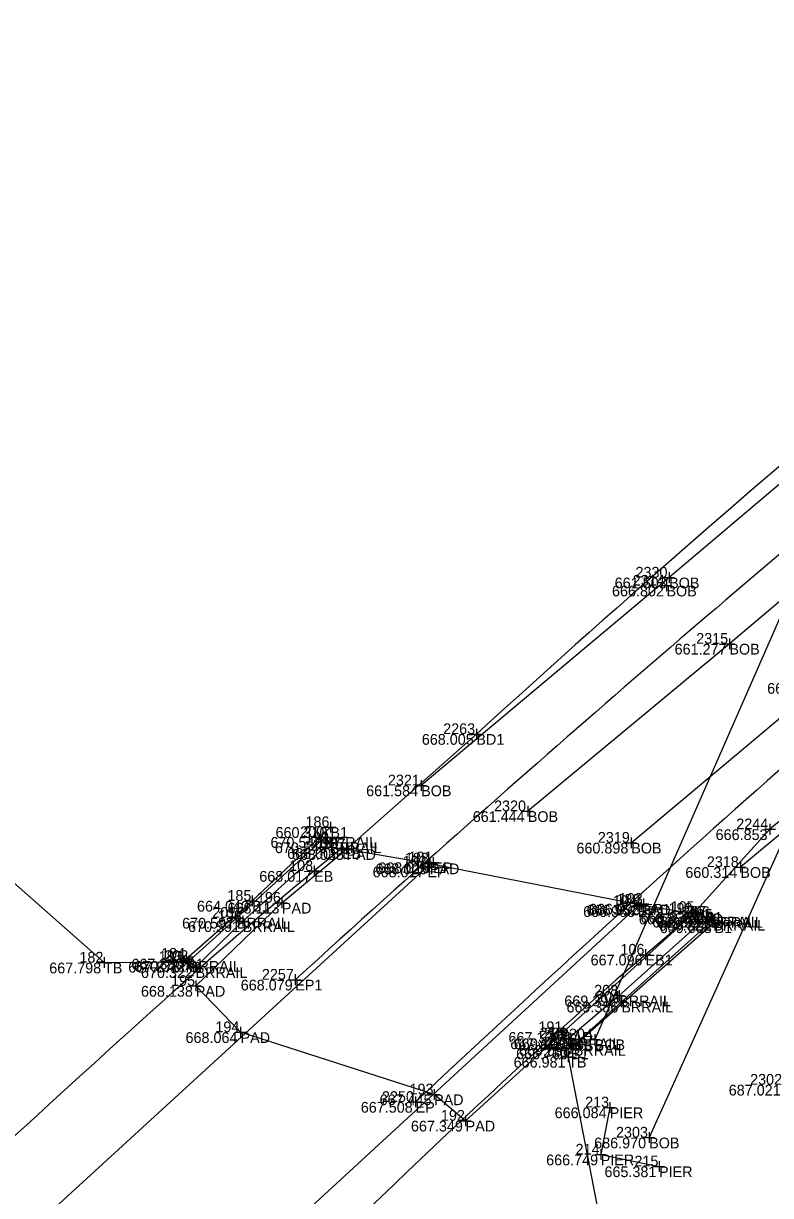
# Model space of a CAD drawing. Extents: x 2197382 to 2204062, y 634117 to 636522.
# Drawn here: x 2202513 to 2202582.6, y 635122.7 to 635231.8 of the extents above; entities that cross this region are included whole.
import ezdxf

# ---------------------------------------------------------------- set-up
doc = ezdxf.new("R2010")
doc.units = 0
for name, color, linetype in [('_CIVIL_CONSTRUCTION', 7, 'Continuous'), ('BR_P_Gen_Approach_Slab', 7, 'Continuous'), ('BR_X_SV_Bottom_of_Beam', 7, 'Continuous'), ('BR_X_SV_Bottom_of_Beam_Text', 7, 'Continuous'), ('BR_X_SV_Deck_Top', 7, 'Continuous'), ('BR_X_SV_Deck_Top_Text', 7, 'Continuous'), ('BR_X_SV_Pier', 7, 'Continuous'), ('BR_X_SV_Rail', 7, 'Continuous'), ('GE_P_Alignment_100_Distances', 7, 'Continuous'), ('GE_X_Alignment', 7, 'Continuous'), ('PF_P_Grade_Line', 7, 'Continuous'), ('RW_X_CL_100_Distances', 7, 'Continuous'), ('RW_X_CL_100_Stations', 7, 'Continuous'), ('SH_Border', 7, 'Continuous'), ('SH_Cut_Line', 7, 'Continuous'), ('SH_Data', 7, 'Continuous'), ('SH_Text', 7, 'Continuous')]:
    doc.layers.add(name, color=color, linetype=linetype)

msp = doc.modelspace()

# ---------------------------------------------------------------- linework, layer by layer
at = {"layer": '_CIVIL_CONSTRUCTION'}
for p, q in [((2202572.62, 635180.24), (2202573.62, 635180.24)), ((2202572.87, 635179.99), (2202572.87, 635178.99)), ((2202573.12, 635180.74), (2202573.12, 635179.74)), ((2202573.12, 635180.24), (2202573.12, 635180.24)), ((2202572.37, 635179.49), (2202573.37, 635179.49)), ((2202572.87, 635179.49), (2202572.87, 635179.49)), ((2202578.73, 635174.58), (2202578.73, 635173.58)), ((2202578.23, 635174.08), (2202579.23, 635174.08)), ((2202578.73, 635174.08), (2202578.73, 635174.08)), ((2202554.67, 635165.67), (2202555.67, 635165.67)), ((2202555.17, 635166.17), (2202555.17, 635165.17)), ((2202555.17, 635165.67), (2202555.17, 635165.67)), ((2202550.03, 635161.39), (2202550.03, 635160.39)), ((2202549.53, 635160.89), (2202550.53, 635160.89)), ((2202550.03, 635160.89), (2202550.03, 635160.89)), ((2202559.96, 635158.99), (2202559.96, 635157.99)), ((2202559.46, 635158.49), (2202560.46, 635158.49)), ((2202559.96, 635158.49), (2202559.96, 635158.49)), ((2202541.08, 635157.01), (2202542.08, 635157.01)), ((2202541.58, 635157.51), (2202541.58, 635156.51)), ((2202541.58, 635157.01), (2202541.58, 635157.01)), ((2202582.01, 635156.81), (2202583.01, 635156.81)), ((2202582.51, 635157.31), (2202582.51, 635156.31)), ((2202582.51, 635156.81), (2202582.51, 635156.81)), ((2202540.6, 635156.09), (2202541.6, 635156.09)), ((2202541.1, 635156.59), (2202541.1, 635155.59)), ((2202541.1, 635156.09), (2202541.1, 635156.09)), ((2202541.52, 635156.09), (2202541.52, 635155.09)), ((2202569.59, 635156.06), (2202569.59, 635155.06)), ((2202541.02, 635155.59), (2202542.02, 635155.59)), ((2202541.52, 635155.59), (2202541.52, 635155.59)), ((2202542.16, 635155.06), (2202543.16, 635155.06)), ((2202542.57, 635154.96), (2202543.57, 635154.96)), ((2202542.66, 635155.56), (2202542.66, 635154.56)), ((2202542.66, 635155.06), (2202542.66, 635155.06)), ((2202543.07, 635155.46), (2202543.07, 635154.46)), ((2202543.07, 635154.96), (2202543.07, 635154.96)), ((2202569.09, 635155.56), (2202570.09, 635155.56)), ((2202569.59, 635155.56), (2202569.59, 635155.56)), ((2202550.34, 635153.63), (2202551.34, 635153.63)), ((2202550.61, 635153.84), (2202550.61, 635152.84)), ((2202550.64, 635153.73), (2202551.64, 635153.73)), ((2202550.84, 635154.13), (2202550.84, 635153.13)), ((2202550.84, 635153.63), (2202550.84, 635153.63)), ((2202551.14, 635154.23), (2202551.14, 635153.23)), ((2202551.14, 635153.73), (2202551.14, 635153.73)), ((2202579.75, 635153.79), (2202579.75, 635152.79)), ((2202539.56, 635152.93), (2202540.56, 635152.93)), ((2202540.06, 635153.43), (2202540.06, 635152.43)), ((2202540.06, 635152.93), (2202540.06, 635152.93)), ((2202550.11, 635153.34), (2202551.11, 635153.34)), ((2202550.61, 635153.34), (2202550.61, 635153.34)), ((2202579.25, 635153.29), (2202580.25, 635153.29)), ((2202579.75, 635153.29), (2202579.75, 635153.29)), ((2202534.28, 635150.65), (2202534.28, 635149.65)), ((2202537.06, 635150.47), (2202537.06, 635149.47)), ((2202570.51, 635150.29), (2202570.51, 635149.29)), ((2202570.72, 635150.37), (2202570.72, 635149.37)), ((2202533.78, 635150.15), (2202534.78, 635150.15)), ((2202534.28, 635150.15), (2202534.28, 635150.15)), ((2202536.56, 635149.97), (2202537.56, 635149.97)), ((2202537.06, 635149.97), (2202537.06, 635149.97)), ((2202569.71, 635149.65), (2202570.71, 635149.65)), ((2202570.01, 635149.79), (2202571.01, 635149.79)), ((2202570.21, 635150.15), (2202570.21, 635149.15)), ((2202570.21, 635149.65), (2202570.21, 635149.65)), ((2202570.22, 635149.87), (2202571.22, 635149.87)), ((2202570.51, 635149.79), (2202570.51, 635149.79)), ((2202570.72, 635149.87), (2202570.72, 635149.87)), ((2202575.4, 635149.46), (2202575.4, 635148.46)), ((2202575.55, 635149.61), (2202575.55, 635148.61)), ((2202576.65, 635149.17), (2202576.65, 635148.17)), ((2202532.37, 635148.57), (2202533.37, 635148.57)), ((2202532.87, 635149.07), (2202532.87, 635148.07)), ((2202532.87, 635148.57), (2202532.87, 635148.57)), ((2202532.92, 635148.25), (2202533.92, 635148.25)), ((2202533.42, 635148.75), (2202533.42, 635147.75)), ((2202533.42, 635148.25), (2202533.42, 635148.25)), ((2202574.9, 635148.96), (2202575.9, 635148.96)), ((2202575.05, 635149.11), (2202576.05, 635149.11)), ((2202575.4, 635148.96), (2202575.4, 635148.96)), ((2202575.55, 635149.11), (2202575.55, 635149.11)), ((2202576.15, 635148.67), (2202577.15, 635148.67)), ((2202576.51, 635148.64), (2202577.51, 635148.64)), ((2202576.65, 635148.67), (2202576.65, 635148.67)), ((2202576.73, 635148.38), (2202577.73, 635148.38)), ((2202576.85, 635148.15), (2202577.85, 635148.15)), ((2202577.01, 635149.14), (2202577.01, 635148.14)), ((2202577.01, 635148.64), (2202577.01, 635148.64)), ((2202577.23, 635148.88), (2202577.23, 635147.88)), ((2202577.23, 635148.38), (2202577.23, 635148.38)), ((2202577.35, 635148.65), (2202577.35, 635147.65)), ((2202577.35, 635148.15), (2202577.35, 635148.15)), ((2202520.5, 635144.9), (2202520.5, 635143.9)), ((2202527.86, 635144.97), (2202527.86, 635143.97)), ((2202528.16, 635145.26), (2202528.16, 635144.26)), ((2202528.4, 635145.05), (2202528.4, 635144.05)), ((2202570.42, 635145.14), (2202571.42, 635145.14)), ((2202570.92, 635145.64), (2202570.92, 635144.64)), ((2202570.92, 635145.14), (2202570.92, 635145.14)), ((2202520, 635144.4), (2202521, 635144.4)), ((2202520.5, 635144.4), (2202520.5, 635144.4)), ((2202527.36, 635144.47), (2202528.36, 635144.47)), ((2202527.66, 635144.76), (2202528.66, 635144.76)), ((2202527.86, 635144.47), (2202527.86, 635144.47)), ((2202527.9, 635144.55), (2202528.9, 635144.55)), ((2202528.16, 635144.76), (2202528.16, 635144.76)), ((2202528.4, 635144.55), (2202528.4, 635144.55)), ((2202528.52, 635143.97), (2202529.52, 635143.97)), ((2202529.02, 635144.47), (2202529.02, 635143.47)), ((2202529.02, 635143.97), (2202529.02, 635143.97)), ((2202529.04, 635142.73), (2202529.04, 635141.73)), ((2202537.81, 635142.81), (2202538.81, 635142.81)), ((2202538.31, 635143.31), (2202538.31, 635142.31)), ((2202538.31, 635142.81), (2202538.31, 635142.81)), ((2202528.54, 635142.23), (2202529.54, 635142.23)), ((2202529.04, 635142.23), (2202529.04, 635142.23)), ((2202568.46, 635141.83), (2202568.46, 635140.83)), ((2202567.96, 635141.33), (2202568.96, 635141.33)), ((2202568.17, 635140.76), (2202569.17, 635140.76)), ((2202568.46, 635141.33), (2202568.46, 635141.33)), ((2202568.67, 635141.26), (2202568.67, 635140.26)), ((2202568.67, 635140.76), (2202568.67, 635140.76)), ((2202533.21, 635138.42), (2202533.21, 635137.42)), ((2202563.26, 635138.43), (2202563.26, 635137.43)), ((2202532.71, 635137.92), (2202533.71, 635137.92)), ((2202533.21, 635137.92), (2202533.21, 635137.92)), ((2202562.76, 635137.93), (2202563.76, 635137.93)), ((2202562.9, 635137.35), (2202563.9, 635137.35)), ((2202563.25, 635137.34), (2202564.25, 635137.34)), ((2202563.26, 635137.93), (2202563.26, 635137.93)), ((2202563.4, 635137.85), (2202563.4, 635136.85)), ((2202563.4, 635137.35), (2202563.4, 635137.35)), ((2202563.75, 635137.84), (2202563.75, 635136.84)), ((2202563.75, 635137.34), (2202563.75, 635137.34)), ((2202564.24, 635137.23), (2202564.24, 635136.23)), ((2202565.69, 635137.25), (2202566.69, 635137.25)), ((2202566.19, 635137.75), (2202566.19, 635136.75)), ((2202566.19, 635137.25), (2202566.19, 635137.25)), ((2202563.48, 635136.4), (2202564.48, 635136.4)), ((2202563.72, 635136.13), (2202563.72, 635135.13)), ((2202563.74, 635136.73), (2202564.74, 635136.73)), ((2202563.98, 635136.9), (2202563.98, 635135.9)), ((2202563.98, 635136.4), (2202563.98, 635136.4)), ((2202564.24, 635136.73), (2202564.24, 635136.73)), ((2202563.22, 635135.63), (2202564.22, 635135.63)), ((2202563.72, 635135.63), (2202563.72, 635135.63)), ((2202549.51, 635131.93), (2202549.51, 635130.93)), ((2202550.73, 635132.13), (2202551.73, 635132.13)), ((2202551.23, 635132.63), (2202551.23, 635131.63)), ((2202551.23, 635132.13), (2202551.23, 635132.13)), ((2202549.01, 635131.43), (2202550.01, 635131.43)), ((2202549.51, 635131.43), (2202549.51, 635131.43)), ((2202567.09, 635130.92), (2202568.09, 635130.92)), ((2202567.59, 635131.42), (2202567.59, 635130.42)), ((2202567.59, 635130.92), (2202567.59, 635130.92)), ((2202553.67, 635129.68), (2202554.67, 635129.68)), ((2202554.17, 635130.18), (2202554.17, 635129.18)), ((2202554.17, 635129.68), (2202554.17, 635129.68)), ((2202571.26, 635128.61), (2202571.26, 635127.61)), ((2202570.76, 635128.11), (2202571.76, 635128.11)), ((2202571.26, 635128.11), (2202571.26, 635128.11)), ((2202566.25, 635126.53), (2202567.25, 635126.53)), ((2202566.75, 635127.03), (2202566.75, 635126.03)), ((2202566.75, 635126.53), (2202566.75, 635126.53)), ((2202571.68, 635125.43), (2202572.68, 635125.43)), ((2202572.18, 635125.93), (2202572.18, 635124.93)), ((2202572.18, 635125.43), (2202572.18, 635125.43))]:
    msp.add_line(p, q, dxfattribs=at)
at = {"layer": 'BR_P_Gen_Approach_Slab'}
msp.add_lwpolyline([(2202543.07, 635154.96), (2202550.84, 635153.63), (2202570.51, 635149.79), (2202575.4, 635148.96), (2202563.26, 635137.93), (2202554.17, 635129.68), (2202551.23, 635132.13), (2202533.21, 635137.92), (2202529.04, 635142.23), (2202537.06, 635149.97)], close=True, dxfattribs=at)
at = {"layer": 'BR_X_SV_Bottom_of_Beam'}
for points in [[(2202698.74, 635432.34), (2202647, 635318.77), (2202622.9, 635265.64), (2202604.22, 635223.89), (2202566.19, 635137.25)], [(2202700.3, 635413.56), (2202652.91, 635308.89), (2202632.96, 635265.28), (2202616.35, 635228.13), (2202571.26, 635128.11)], [(2202606.61, 635208.62), (2202603.7, 635205.92), (2202603.43, 635205.67), (2202587.81, 635192.67), (2202573.12, 635180.24), (2202550.03, 635160.89)], [(2202617.23, 635206.4), (2202614, 635203.65), (2202596.42, 635189.02), (2202578.73, 635174.08), (2202559.96, 635158.49)], [(2202569.59, 635155.56), (2202587.35, 635170.43), (2202603.51, 635184.09), (2202612.29, 635191.47), (2202624.52, 635201.84), (2202627.43, 635204.04)], [(2202639.19, 635203), (2202635.46, 635199.72), (2202613.03, 635181.1), (2202603.37, 635172.99), (2202595.3, 635166.21), (2202579.75, 635153.29)]]:
    msp.add_lwpolyline(points, dxfattribs=at)
at = {"layer": 'BR_X_SV_Deck_Top'}
for p, q in [((2202555.17, 635165.67), (2202543.07, 635154.96)), ((2202582.51, 635156.81), (2202575.4, 635148.96))]:
    msp.add_line(p, q, dxfattribs=at)
for points in [[(2202458.05, 635216.68), (2202477.12, 635219.98), (2202511.72, 635243.78), (2202554.96, 635262.3), (2202588.01, 635280.67), (2202608.34, 635292.39), (2202640.83, 635312.14), (2202668.15, 635329.95), (2202698.57, 635351.31), (2202722.13, 635368.65), (2202754.6, 635393.43), (2202777.49, 635412.29), (2202789.61, 635422.64)], [(2202895.36, 635391.81), (2202885.35, 635387.33), (2202865.19, 635377.21), (2202839.04, 635363.76), (2202813.1, 635349.72), (2202789.18, 635336.14), (2202762.39, 635320.29), (2202740.67, 635306.56), (2202716.63, 635290.83), (2202693.39, 635275.34), (2202664.57, 635254.79), (2202633.54, 635231.77), (2202595.89, 635201.64), (2202569.4, 635178.62), (2202555.17, 635165.67)], [(2202923.18, 635376.2), (2202906.17, 635369.08), (2202881.49, 635355.93), (2202846.74, 635338.13), (2202819.01, 635322.65), (2202790.14, 635306.09), (2202754.02, 635283.78), (2202709.42, 635255.58), (2202663.28, 635220.88), (2202620.57, 635187.91), (2202595.28, 635167.4), (2202582.51, 635156.81)]]:
    msp.add_open_spline(points, degree=3, dxfattribs=at)
at = {"layer": 'BR_X_SV_Pier'}
msp.add_lwpolyline([(2202567.59, 635130.92), (2202566.75, 635126.53), (2202572.18, 635125.43)], dxfattribs=at)
at = {"layer": 'BR_X_SV_Rail'}
for points in [[(2202529.02, 635143.97), (2202533.42, 635148.25), (2202541.52, 635155.59), (2202541.1, 635156.09), (2202532.87, 635148.57), (2202528.4, 635144.55)], [(2202564.24, 635136.73), (2202568.67, 635140.76), (2202577.23, 635148.38), (2202577.01, 635148.64), (2202576.65, 635148.67), (2202568.46, 635141.33), (2202563.75, 635137.34)]]:
    msp.add_lwpolyline(points, close=True, dxfattribs=at)
at = {"layer": 'GE_P_Alignment_100_Distances'}
for p, q in [((2202551.14, 635153.73), (2202550.61, 635153.34)), ((2202550.61, 635153.34), (2202514.19, 635120)), ((2202570.21, 635149.65), (2202525.02, 635108.11)), ((2202570.72, 635149.87), (2202570.21, 635149.65))]:
    msp.add_line(p, q, dxfattribs=at)
for points in [[(2202457.67, 635223.28), (2202466.48, 635226.87), (2202500.46, 635242.35), (2202539.48, 635261.18), (2202573.06, 635279.52), (2202585.61, 635286.63), (2202599.84, 635294.84), (2202617.62, 635305.23), (2202642.29, 635320.4), (2202667.37, 635336.77), (2202691.72, 635353.63), (2202713.41, 635369.4), (2202739.64, 635388.97), (2202758.66, 635404.28), (2202770.06, 635413.81)], [(2202926.99, 635398.22), (2202911.05, 635391.27), (2202884.78, 635379.22), (2202850.25, 635362.17), (2202828.22, 635350.04), (2202808.09, 635339.2), (2202790.85, 635329.04), (2202764, 635313.32), (2202738.78, 635297.64), (2202713.05, 635280.58), (2202697.02, 635269.6), (2202684.53, 635260.86), (2202668.99, 635249.75), (2202642.65, 635230.81), (2202596.56, 635193.89), (2202560.68, 635163.16), (2202538.31, 635142.81)], [(2202919.5, 635378.37), (2202901.45, 635370.68), (2202875.94, 635356.88), (2202844.59, 635341.6), (2202825.86, 635330.82), (2202809.47, 635322.02), (2202780.05, 635304.41), (2202746.06, 635283), (2202707.72, 635258.18), (2202682.24, 635240.21), (2202658.95, 635222.26), (2202614.14, 635189.25), (2202577.35, 635157.52), (2202549.51, 635131.43)]]:
    msp.add_open_spline(points, degree=3, dxfattribs=at)
at = {"layer": 'GE_X_Alignment'}
for p, q in [((2202542.66, 635155.06), (2202540.06, 635152.93)), ((2202575.55, 635149.11), (2202570.92, 635145.14))]:
    msp.add_line(p, q, dxfattribs=at)
for points in [[(2202540.06, 635152.93), (2202529.43, 635144.25), (2202507.23, 635123.46), (2202471.72, 635092.05), (2202435.62, 635056.76), (2202402.1, 635018.87), (2202368.73, 634981.48), (2202336.15, 634943.25), (2202304.62, 634904.21), (2202274.11, 634864.33), (2202244.37, 634823.83), (2202215.65, 634782.83), (2202187.65, 634741.05), (2202161.54, 634698.56), (2202134.84, 634656), (2202111.41, 634611.66), (2202087.71, 634567.52), (2202064.97, 634523.35), (2202044.2, 634477.97), (2202023.42, 634432.25), (2202003.66, 634386.18), (2201990.91, 634355.55), (2201984.79, 634340.33)], [(2202570.92, 635145.14), (2202556.1, 635132.41), (2202530.6, 635107.02), (2202492.19, 635071.28), (2202457.98, 635035.82), (2202424.73, 634999.38), (2202391.64, 634962.22), (2202359.56, 634924.46), (2202328.32, 634885.6), (2202298.37, 634846.53), (2202268.85, 634806.21), (2202240.94, 634765.59), (2202212.91, 634724.71), (2202187.2, 634682.69), (2202161.14, 634640.35), (2202137.99, 634596.95), (2202114.64, 634553.56), (2202092.28, 634509.95), (2202071.73, 634464.7), (2202050.81, 634420.11), (2202031.84, 634374.34), (2202014.23, 634328.21), (2201997.98, 634281.03), (2201983.22, 634233.69), (2201972.74, 634202.38), (2201968.03, 634186.79)]]:
    msp.add_open_spline(points, degree=3, dxfattribs=at)
at = {"layer": 'PF_P_Grade_Line'}
for points in [[(2202484.34, 635172.09), (2202502.01, 635160.7), (2202520.5, 635144.4), (2202527.86, 635144.47)], [(2202563.72, 635135.63), (2202567.86, 635114.33), (2202576.61, 635092), (2202580.49, 635062.03)]]:
    msp.add_lwpolyline(points, dxfattribs=at)
at = {"layer": 'SH_Text'}
for points in [[(2202528.16, 635144.76), (2202534.28, 635150.15), (2202541.58, 635157.01)], [(2202563.4, 635137.35), (2202563.98, 635136.4), (2202577.35, 635148.15)]]:
    msp.add_lwpolyline(points, dxfattribs=at)

# ---------------------------------------------------------------- texts
at = {"layer": 'BR_X_SV_Bottom_of_Beam_Text'}
for s, p in [('2330', (2202569.99, 635180.24)), ('661.503', (2202568.05, 635179.24)), ('2314', (2202569.73, 635179.49)), ('BOB', (2202573.12, 635179.24)), ('666.802', (2202567.8, 635178.49)), ('BOB', (2202572.87, 635178.49)), ('2315', (2202575.64, 635174.08)), ('661.277', (2202573.63, 635173.08)), ('BOB', (2202578.73, 635173.08)), ('660.708', (2202582.25, 635169.43)), ('2321', (2202546.93, 635160.89)), ('661.584', (2202544.91, 635159.89)), ('BOB', (2202550.03, 635159.89)), ('2320', (2202556.82, 635158.49)), ('661.444', (2202554.83, 635157.49)), ('BOB', (2202559.96, 635157.49)), ('2319', (2202566.48, 635155.56)), ('660.898', (2202564.49, 635154.56)), ('BOB', (2202569.59, 635154.56)), ('2318', (2202576.63, 635153.29)), ('660.314', (2202574.63, 635152.29)), ('BOB', (2202579.75, 635152.29)), ('2304', (2202563.05, 635137.25)), ('686.795', (2202561.12, 635136.25)), ('BOB', (2202566.19, 635136.25)), ('2302', (2202580.66, 635133.03)), ('687.021', (2202578.67, 635132.03)), ('2303', (2202568.17, 635128.11)), ('686.970', (2202566.14, 635127.11)), ('BOB', (2202571.26, 635127.11))]:
    msp.add_text(s, height=1, dxfattribs=at).set_placement(p)
at = {"layer": 'BR_X_SV_Deck_Top_Text'}
for s, p in [('2263', (2202552.08, 635165.67)), ('668.005', (2202550.09, 635164.68)), ('BD1', (2202555.17, 635164.68)), ('666.853', (2202577.45, 635155.81)), ('2244', (2202579.37, 635156.81))]:
    msp.add_text(s, height=1, dxfattribs=at).set_placement(p)
at = {"layer": 'RW_X_CL_100_Distances'}
for s, p in [('213', (2202565.3, 635130.92)), ('666.084', (2202562.46, 635129.92)), ('PIER', (2202567.59, 635129.92)), ('214', (2202564.41, 635126.53)), ('666.749', (2202561.67, 635125.53)), ('PIER', (2202566.75, 635125.53)), ('215', (2202569.89, 635125.43)), ('665.381', (2202567.1, 635124.43)), ('PIER', (2202572.18, 635124.43))]:
    msp.add_text(s, height=1, dxfattribs=at).set_placement(p)
at = {"layer": 'RW_X_CL_100_Stations'}
for s, p in [('200', (2202538.77, 635156.09)), ('670.548', (2202536, 635155.09)), ('199', (2202539.21, 635155.59)), ('BRRAIL', (2202541.1, 635155.09)), ('670.546', (2202536.41, 635154.59)), ('BRRAIL', (2202541.52, 635154.59)), ('201', (2202530.57, 635148.57)), ('198', (2202531.09, 635148.25)), ('207', (2202574.34, 635148.67)), ('206', (2202574.68, 635148.64)), ('205', (2202574.94, 635148.38)), ('670.597', (2202527.77, 635147.57)), ('670.591', (2202528.33, 635147.25)), ('BRRAIL', (2202532.87, 635147.57)), ('BRRAIL', (2202533.42, 635147.25)), ('669.328', (2202571.55, 635147.67)), ('669.322', (2202571.93, 635147.64)), ('669.321', (2202572.15, 635147.38)), ('BRRAIL', (2202576.65, 635147.67)), ('BRRAIL', (2202577.01, 635147.64)), ('BRRAIL', (2202577.23, 635147.38)), ('202', (2202526.11, 635144.55)), ('197', (2202526.7, 635143.97)), ('670.321', (2202523.32, 635143.55)), ('670.322', (2202523.94, 635142.97)), ('BRRAIL', (2202528.4, 635143.55)), ('BRRAIL', (2202529.02, 635142.97)), ('208', (2202566.14, 635141.33)), ('204', (2202566.32, 635140.76)), ('669.396', (2202563.36, 635140.33)), ('669.386', (2202563.56, 635139.76)), ('BRRAIL', (2202568.46, 635140.33)), ('BRRAIL', (2202568.67, 635139.76)), ('209', (2202561.44, 635137.34)), ('669.109', (2202558.66, 635136.34)), ('203', (2202561.95, 635136.73)), ('BRRAIL', (2202563.75, 635136.34)), ('669.098', (2202559.14, 635135.73)), ('BRRAIL', (2202564.24, 635135.73))]:
    msp.add_text(s, height=1, dxfattribs=at).set_placement(p)
at = {"layer": 'SH_Border'}
for s, p in [('B1', (2202541.58, 635156.01)), ('EB', (2202542.66, 635154.06)), ('PAD', (2202543.07, 635153.96)), ('PAD', (2202550.84, 635152.63)), ('EP', (2202551.14, 635152.73)), ('EB', (2202540.06, 635151.93)), ('EP', (2202550.61, 635152.34)), ('B1', (2202534.28, 635149.15)), ('PAD', (2202537.06, 635148.97)), ('EP1', (2202570.21, 635148.65)), ('PAD', (2202570.51, 635148.79)), ('EP1', (2202570.72, 635148.87)), ('PAD', (2202575.4, 635147.96)), ('EB1', (2202575.55, 635148.11)), ('B1', (2202577.35, 635147.15)), ('EB1', (2202570.92, 635144.14)), ('TB', (2202520.5, 635143.4)), ('TB', (2202527.86, 635143.47)), ('B1', (2202528.16, 635143.76)), ('EP1', (2202538.31, 635141.81)), ('PAD', (2202529.04, 635141.23)), ('PAD', (2202533.21, 635136.92)), ('PAD', (2202563.26, 635136.93)), ('B1', (2202563.4, 635136.35)), ('B1', (2202563.98, 635135.4)), ('TB', (2202563.72, 635134.63)), ('PAD', (2202551.23, 635131.13)), ('EP', (2202549.51, 635130.43)), ('PAD', (2202554.17, 635128.68))]:
    msp.add_text(s, height=1, dxfattribs=at).set_placement(p)
at = {"layer": 'SH_Cut_Line'}
for s, p in [('186', (2202539.26, 635157.01)), ('107', (2202540.34, 635155.06)), ('187', (2202540.76, 635154.96)), ('188', (2202548.52, 635153.63)), ('101', (2202548.84, 635153.73)), ('108', (2202537.74, 635152.93)), ('102', (2202548.31, 635153.34)), ('185', (2202531.99, 635150.15)), ('196', (2202534.74, 635149.97)), ('104', (2202567.87, 635149.65)), ('189', (2202568.21, 635149.79)), ('103', (2202568.43, 635149.87)), ('190', (2202573.06, 635148.96)), ('105', (2202573.26, 635149.11)), ('212', (2202575.06, 635148.15)), ('106', (2202568.59, 635145.14)), ('182', (2202518.21, 635144.4)), ('183', (2202525.58, 635144.47)), ('184', (2202525.82, 635144.76)), ('2257', (2202535.2, 635142.81)), ('195', (2202526.75, 635142.23)), ('194', (2202530.87, 635137.92)), ('191', (2202560.95, 635137.93)), ('210', (2202561.06, 635137.35)), ('211', (2202561.68, 635136.4)), ('216', (2202561.4, 635135.63)), ('193', (2202548.95, 635132.13)), ('2250', (2202546.38, 635131.43)), ('192', (2202551.87, 635129.68))]:
    msp.add_text(s, height=1, dxfattribs=at).set_placement(p)
at = {"layer": 'SH_Data'}
for s, p in [('660.310', (2202536.47, 635156.01)), ('668.006', (2202537.55, 635154.06)), ('668.035', (2202538, 635153.96)), ('668.025', (2202545.77, 635152.63)), ('668.010', (2202546.03, 635152.73)), ('668.017', (2202534.96, 635151.93)), ('668.017', (2202545.51, 635152.34)), ('664.040', (2202529.16, 635149.15)), ('668.113', (2202532, 635148.97)), ('666.966', (2202565.11, 635148.65)), ('666.952', (2202565.44, 635148.79)), ('666.995', (2202565.65, 635148.87)), ('666.856', (2202570.29, 635147.96)), ('666.839', (2202570.46, 635148.11)), ('659.068', (2202572.25, 635147.15)), ('667.096', (2202565.81, 635144.14)), ('667.798', (2202515.4, 635143.4)), ('667.878', (2202522.76, 635143.47)), ('667.830', (2202523.05, 635143.76)), ('668.079', (2202533.23, 635141.81)), ('668.138', (2202523.94, 635141.23)), ('668.064', (2202528.09, 635136.92)), ('667.138', (2202558.16, 635136.93)), ('667.082', (2202558.32, 635136.35)), ('666.760', (2202558.87, 635135.4)), ('666.981', (2202558.64, 635134.63)), ('667.445', (2202546.16, 635131.13)), ('667.508', (2202544.41, 635130.43)), ('667.349', (2202549.08, 635128.68))]:
    msp.add_text(s, height=1, dxfattribs=at).set_placement(p)

doc.saveas('drawing.dxf')
